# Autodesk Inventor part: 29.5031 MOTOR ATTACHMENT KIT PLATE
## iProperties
Created: 2006-12
Part Number: 29.5031 MOTOR ATTACHMENT KIT PLATE
Material: Steel
Document SubType Name: Modeling
Designer: Andy Moles
Mass: 1604.76 g
Surface Area: 1099.12 cm^2
Volume: 204.428 cm^3
Density: 7.85 g/cm^3
Author: Andy Moles
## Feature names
1. Extrusion1
